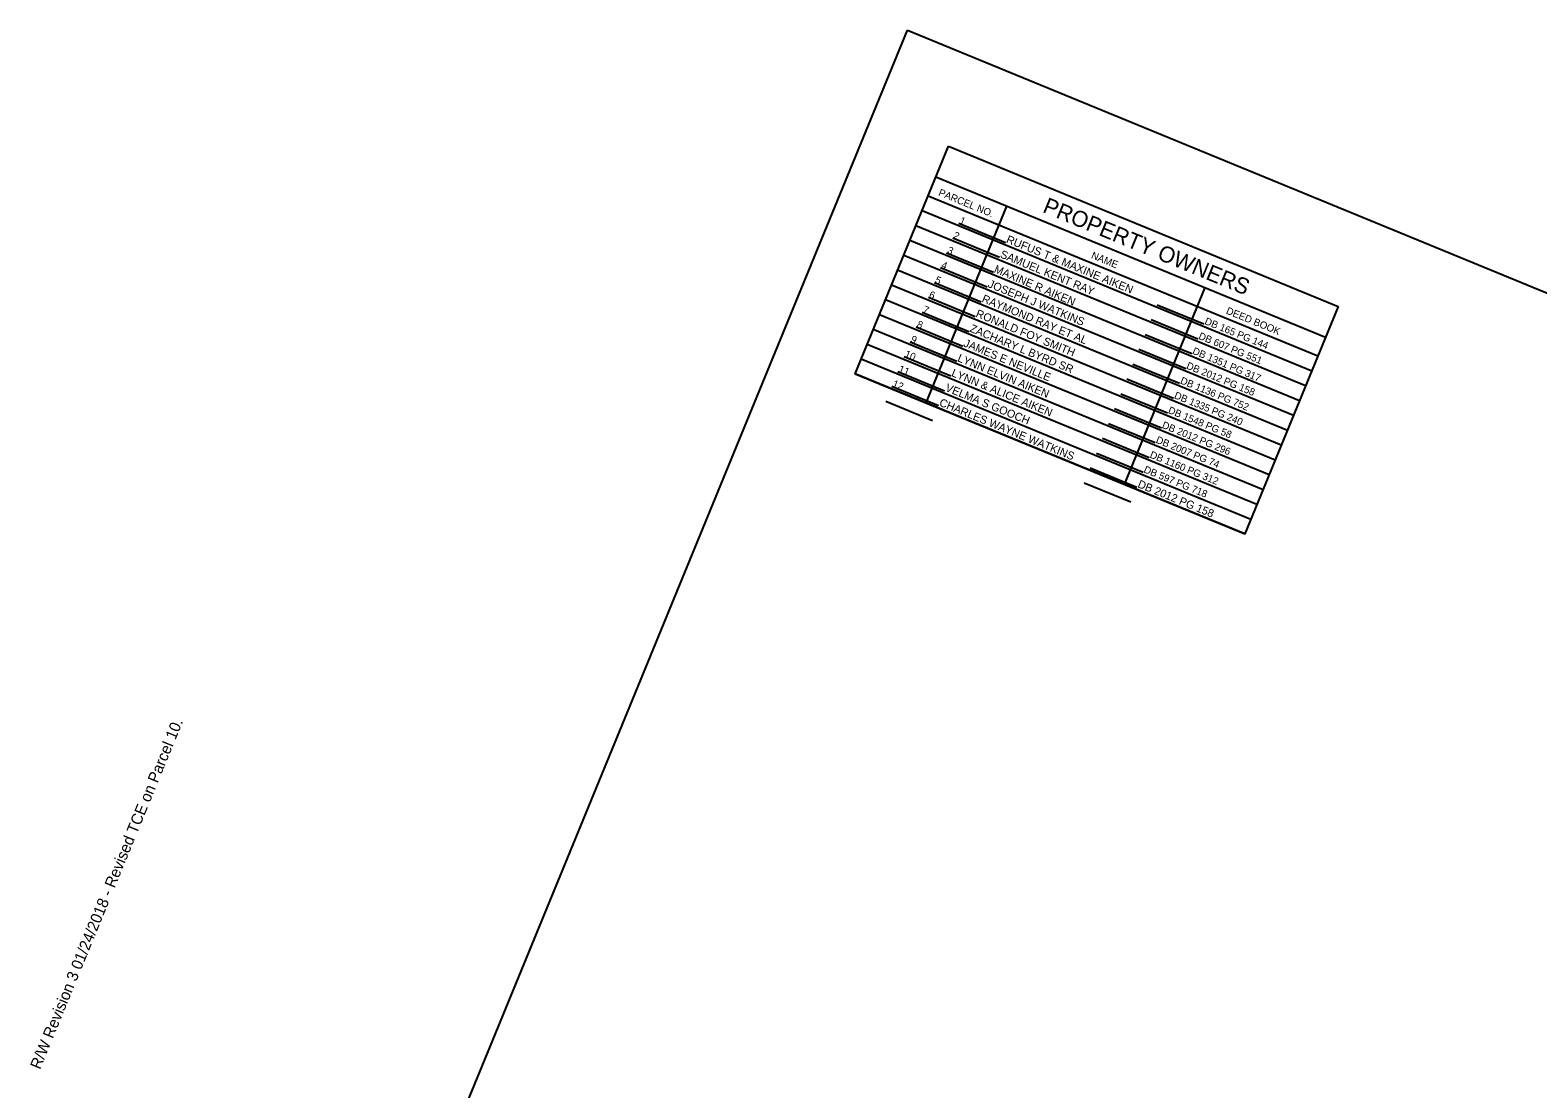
# Model space of a CAD drawing. Extents: x 2090082 to 2091964, y 863291 to 864736.
# Drawn here: x 2090082 to 2091023, y 864075 to 864736 of the extents above; entities that cross this region are included whole.
import ezdxf

# ---------------------------------------------------------------- set-up
doc = ezdxf.new("R2010")
doc.units = 0
for name, color, linetype in [('Exist Property Deed Book Text', 7, 'Continuous'), ('Exist Property Owner Text', 7, 'Continuous'), ('Prop DSN Text', 7, 'Continuous'), ('Scratch_Level_8', 7, 'Continuous'), ('Sheet Clip Boundary CELL', 7, 'Continuous')]:
    doc.layers.add(name, color=color, linetype=linetype)

msp = doc.modelspace()

# ---------------------------------------------------------------- linework, layer by layer
at = {"layer": 'Exist Property Owner Text'}
for p, q in [((2090647.35, 864644.16), (2090890.48, 864544.31)), ((2090642.54, 864632.43), (2090885.67, 864532.58)), ((2090638.74, 864623.18), (2090881.87, 864523.33)), ((2090691.48, 864626.04), (2090641.08, 864503.31)), ((2090634.94, 864613.93), (2090878.07, 864514.08)), ((2090631.14, 864604.68), (2090874.27, 864504.83)), ((2090627.34, 864595.43), (2090870.47, 864495.58)), ((2090623.54, 864586.18), (2090866.67, 864486.33)), ((2090619.74, 864576.93), (2090862.87, 864477.08)), ((2090615.95, 864567.68), (2090859.07, 864467.83)), ((2090815.28, 864575.19), (2090764.88, 864452.46)), ((2090612.15, 864558.43), (2090855.28, 864458.58)), ((2090608.35, 864549.18), (2090851.48, 864449.33)), ((2090604.55, 864539.93), (2090847.68, 864440.08)), ((2090600.75, 864530.68), (2090843.88, 864430.83)), ((2090596.95, 864521.43), (2090840.08, 864421.58))]:
    msp.add_line(p, q, dxfattribs=at)
msp.add_lwpolyline([(2090655.22, 864663.3), (2090898.34, 864563.45), (2090840.08, 864421.58), (2090596.95, 864521.43)], close=True, dxfattribs=at)
at = {"layer": 'Scratch_Level_8'}
for p, q in [((2090661.69, 864615.37), (2090690.84, 864603.4)), ((2090657.9, 864606.12), (2090687.04, 864594.15)), ((2090654.1, 864596.87), (2090683.24, 864584.9)), ((2090650.3, 864587.62), (2090679.44, 864575.65)), ((2090646.5, 864578.37), (2090675.64, 864566.4)), ((2090642.7, 864569.12), (2090671.84, 864557.15)), ((2090638.9, 864559.87), (2090668.04, 864547.9)), ((2090785.5, 864564.52), (2090814.64, 864552.55)), ((2090635.1, 864550.62), (2090664.24, 864538.65)), ((2090781.7, 864555.27), (2090810.84, 864543.3)), ((2090631.3, 864541.37), (2090660.45, 864529.4)), ((2090777.9, 864546.02), (2090807.04, 864534.05)), ((2090627.5, 864532.11), (2090656.65, 864520.15)), ((2090774.1, 864536.77), (2090803.24, 864524.8)), ((2090623.7, 864522.86), (2090652.85, 864510.9)), ((2090770.3, 864527.52), (2090799.45, 864515.55)), ((2090619.91, 864513.61), (2090649.05, 864501.65)), ((2090766.5, 864518.27), (2090795.65, 864506.3)), ((2090616.11, 864504.36), (2090645.25, 864492.4)), ((2090762.7, 864509.02), (2090791.85, 864497.05)), ((2090758.91, 864499.77), (2090788.05, 864487.8)), ((2090755.11, 864490.52), (2090784.25, 864478.55)), ((2090751.31, 864481.27), (2090780.45, 864469.3)), ((2090747.51, 864472.02), (2090776.65, 864460.05)), ((2090739.91, 864453.52), (2090769.05, 864441.55)), ((2090743.71, 864462.77), (2090772.85, 864450.8))]:
    msp.add_line(p, q, dxfattribs=at)
at = {"layer": 'Sheet Clip Boundary CELL'}
msp.add_lwpolyline([(2090629.62, 864735.74), (2091664.37, 864310.58), (2091646.68, 863909.78), (2091445.4, 863779.47), (2091216.58, 863496.49), (2090278.84, 863881.61)], close=True, dxfattribs=at)

# ---------------------------------------------------------------- texts
at = {"layer": 'Exist Property Deed Book Text'}
for s, height, rotation, p in [('PARCEL NO.', 4.5, 337.75557, (2090648.59, 864632.78)), ('PROPERTY OWNERS', 10, 337.67243, (2090713.42, 864622.47)), ('1', 4.5, 337.75557, (2090661.69, 864615.37)), ('2', 4.5, 337.75557, (2090657.9, 864606.12)), ('3', 4.5, 337.75557, (2090654.1, 864596.87)), ('NAME', 4.5, 337.75557, (2090743.9, 864593.64)), ('4', 4.5, 337.75557, (2090650.3, 864587.62)), ('5', 4.5, 337.75557, (2090646.5, 864578.37)), ('6', 4.5, 337.75557, (2090642.7, 864569.12)), ('7', 4.5, 337.75557, (2090638.9, 864559.87)), ('DEED BOOK', 4.5, 337.75557, (2090828.05, 864559.08)), ('8', 4.5, 337.75557, (2090635.1, 864550.62)), ('DB 165 PG 144', 4.5, 337.75557, (2090814.64, 864552.55)), ('9', 4.5, 337.75557, (2090631.3, 864541.37)), ('DB 607 PG 551', 4.5, 337.67243, (2090810.84, 864543.3)), ('10', 4.5, 337.75557, (2090627.5, 864532.11)), ('DB 2012 PG 158', 4.5, 337.67243, (2090803.24, 864524.8)), ('DB 1351 PG 317', 4.5, 337.00917, (2090807.04, 864534.05)), ('11', 4.5, 337.75557, (2090623.7, 864522.86)), ('DB 1136 PG 752', 4.5, 337.67243, (2090799.45, 864515.55)), ('12', 4.5, 337.75557, (2090619.91, 864513.61)), ('DB 1335 PG 240', 4.5, 337.67243, (2090795.65, 864506.3)), ('DB 1548 PG 58', 4.5, 337.67243, (2090791.85, 864497.05)), ('DB 2012 PG 296', 4.5, 337.67243, (2090788.05, 864487.8)), ('DB 2007 PG 74', 4.5, 337.67243, (2090784.25, 864478.55)), ('DB 1160 PG 312', 4.5, 337.67243, (2090780.45, 864469.3)), ('DB 597 PG 718', 4.5, 337.67243, (2090776.65, 864460.05)), ('DB 2012 PG 158', 5, 337.67243, (2090772.85, 864450.8))]:
    msp.add_text(s, height=height, rotation=rotation, dxfattribs=at).set_placement(p)
at = {"layer": 'Exist Property Owner Text'}
for s, rotation, p in [('RUFUS T & MAXINE AIKEN', 337.75557, (2090690.84, 864603.4)), ('SAMUEL KENT RAY', 337.67243, (2090687.04, 864594.15)), ('MAXINE R AIKEN', 337.00917, (2090683.24, 864584.9)), ('JOSEPH J WATKINS', 337.67243, (2090679.44, 864575.65)), ('RAYMOND RAY ET AL', 337.67243, (2090675.64, 864566.4)), ('RONALD FOY SMITH', 337.67243, (2090671.84, 864557.15)), ('ZACHARY L BYRD SR', 337.67243, (2090668.04, 864547.9)), ('JAMES E NEVILLE', 337.67243, (2090664.24, 864538.65)), ('LYNN ELVIN AIKEN', 337.67243, (2090660.45, 864529.4)), ('LYNN & ALICE AIKEN', 337.67243, (2090656.65, 864520.15)), ('VELMA S GOOCH', 337.67243, (2090652.85, 864510.9)), ('CHARLES WAYNE WATKINS', 337.67243, (2090649.05, 864501.65))]:
    msp.add_text(s, height=5, rotation=rotation, dxfattribs=at).set_placement(p)
at = {"layer": 'Prop DSN Text'}
msp.add_text('R/W Revision 3 01/24/2018 - Revised TCE on Parcel 10.', height=7, rotation=67.67243, dxfattribs=at).set_placement((2090088.52, 864087.16))

doc.saveas('drawing.dxf')
